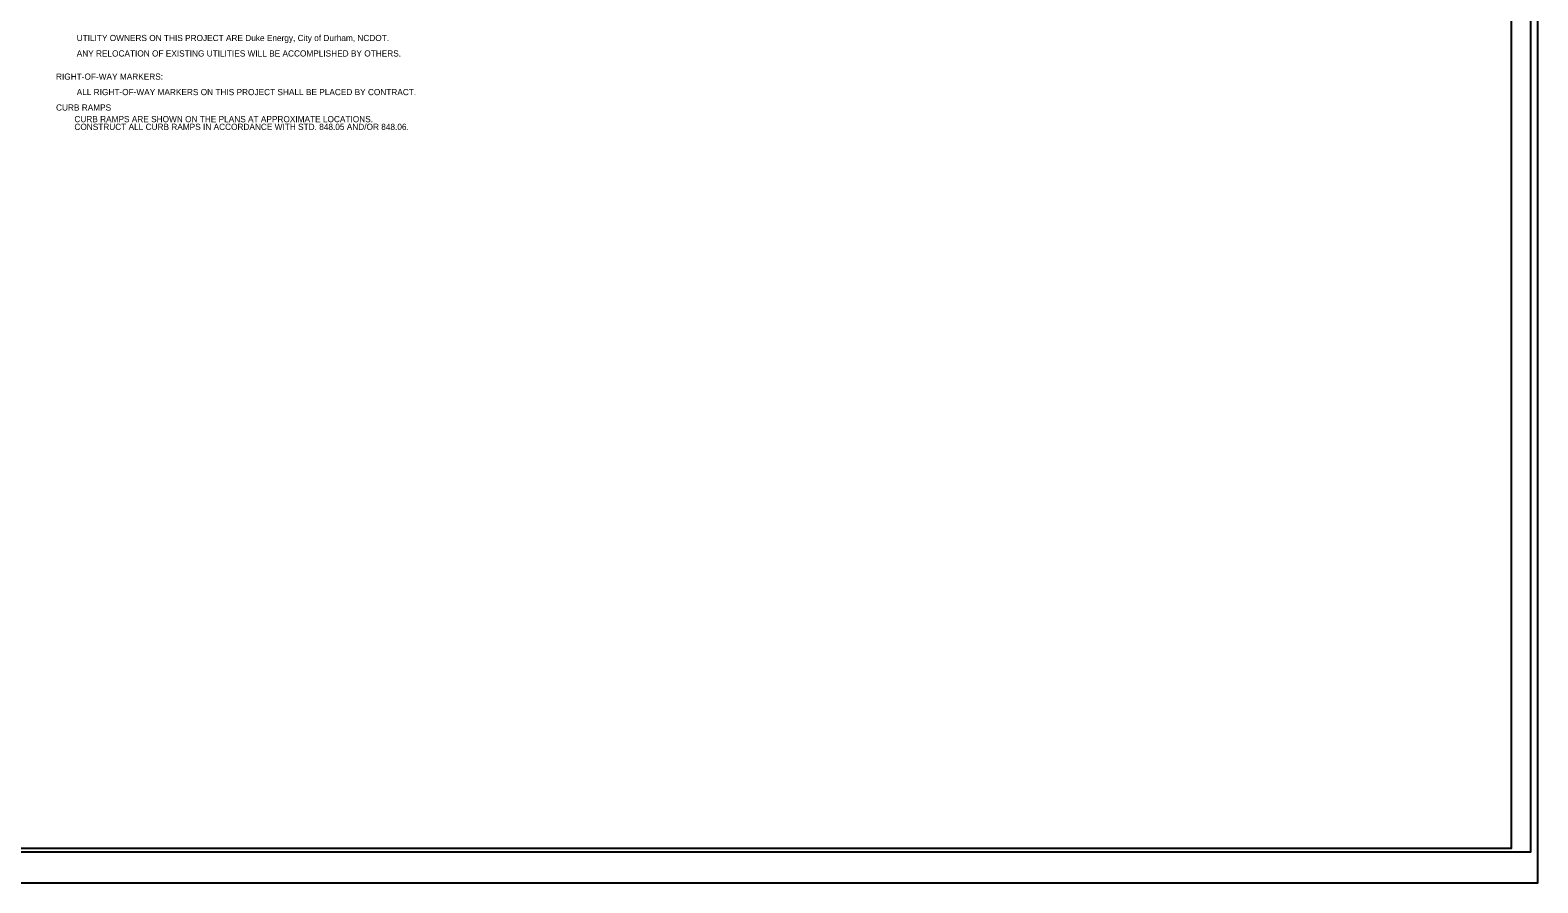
# Model space of a CAD drawing. Extents: x 573851.6 to 573885.3, y -53299.4 to -53277.5.
# Drawn here: x 573865.75 to 573885.26, y -53299.45 to -53288.41 of the extents above; entities that cross this region are included whole.
import ezdxf

# ---------------------------------------------------------------- set-up
doc = ezdxf.new("R2010")
doc.units = 0
for name, color, linetype in [('Default', 7, 'Continuous'), ('Old_Level_2', 7, 'Continuous'), ('Old_Level_4', 7, 'Continuous'), ('Sheet Cutting Line CELL', 7, 'Continuous'), ('Sheet Plot Border Inside CELL', 7, 'Continuous')]:
    doc.layers.add(name, color=color, linetype=linetype)

msp = doc.modelspace()

# ---------------------------------------------------------------- linework, layer by layer
at = {"layer": 'Old_Level_2'}
msp.add_lwpolyline([(573884.92, -53277.999), (573854.92, -53277.999), (573854.92, -53298.999), (573884.92, -53298.999)], close=True, dxfattribs=at)
at = {"layer": 'Old_Level_4'}
msp.add_lwpolyline([(573851.59, -53299.449), (573885.26, -53299.449), (573885.26, -53277.549), (573851.59, -53277.549)], close=True, dxfattribs=at)
at = {"layer": 'Sheet Cutting Line CELL'}
msp.add_line((573851.59, -53299.449), (573885.26, -53299.449), dxfattribs=at)
at = {"layer": 'Sheet Plot Border Inside CELL'}
msp.add_lwpolyline([(573851.85, -53299.049), (573885.17, -53299.049), (573885.17, -53277.949), (573851.85, -53277.949)], close=True, dxfattribs=at)

# ---------------------------------------------------------------- texts
at = {"layer": 'Default'}
for s, p in [('         UTILITY OWNERS ON THIS PROJECT ARE Duke Energy, City of Durham, NCDOT.', (573866.085, -53288.554)), ('         ANY RELOCATION OF EXISTING UTILITIES WILL BE ACCOMPLISHED BY OTHERS.  ', (573866.085, -53288.754)), ('RIGHT-OF-WAY MARKERS:  ', (573866.085, -53289.054)), ('         ALL RIGHT-OF-WAY MARKERS ON THIS PROJECT SHALL BE PLACED BY CONTRACT.  ', (573866.085, -53289.254)), ('CURB RAMPS', (573866.085, -53289.454)), ('        CURB RAMPS ARE SHOWN ON THE PLANS AT APPROXIMATE LOCATIONS.', (573866.085, -53289.604)), ('        CONSTRUCT ALL CURB RAMPS IN ACCORDANCE WITH STD. 848.05 AND/OR 848.06.', (573866.085, -53289.704))]:
    msp.add_text(s, height=0.08, dxfattribs=at).set_placement(p)

doc.saveas('drawing.dxf')
